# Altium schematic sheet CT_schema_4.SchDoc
size 578 x 363 mm
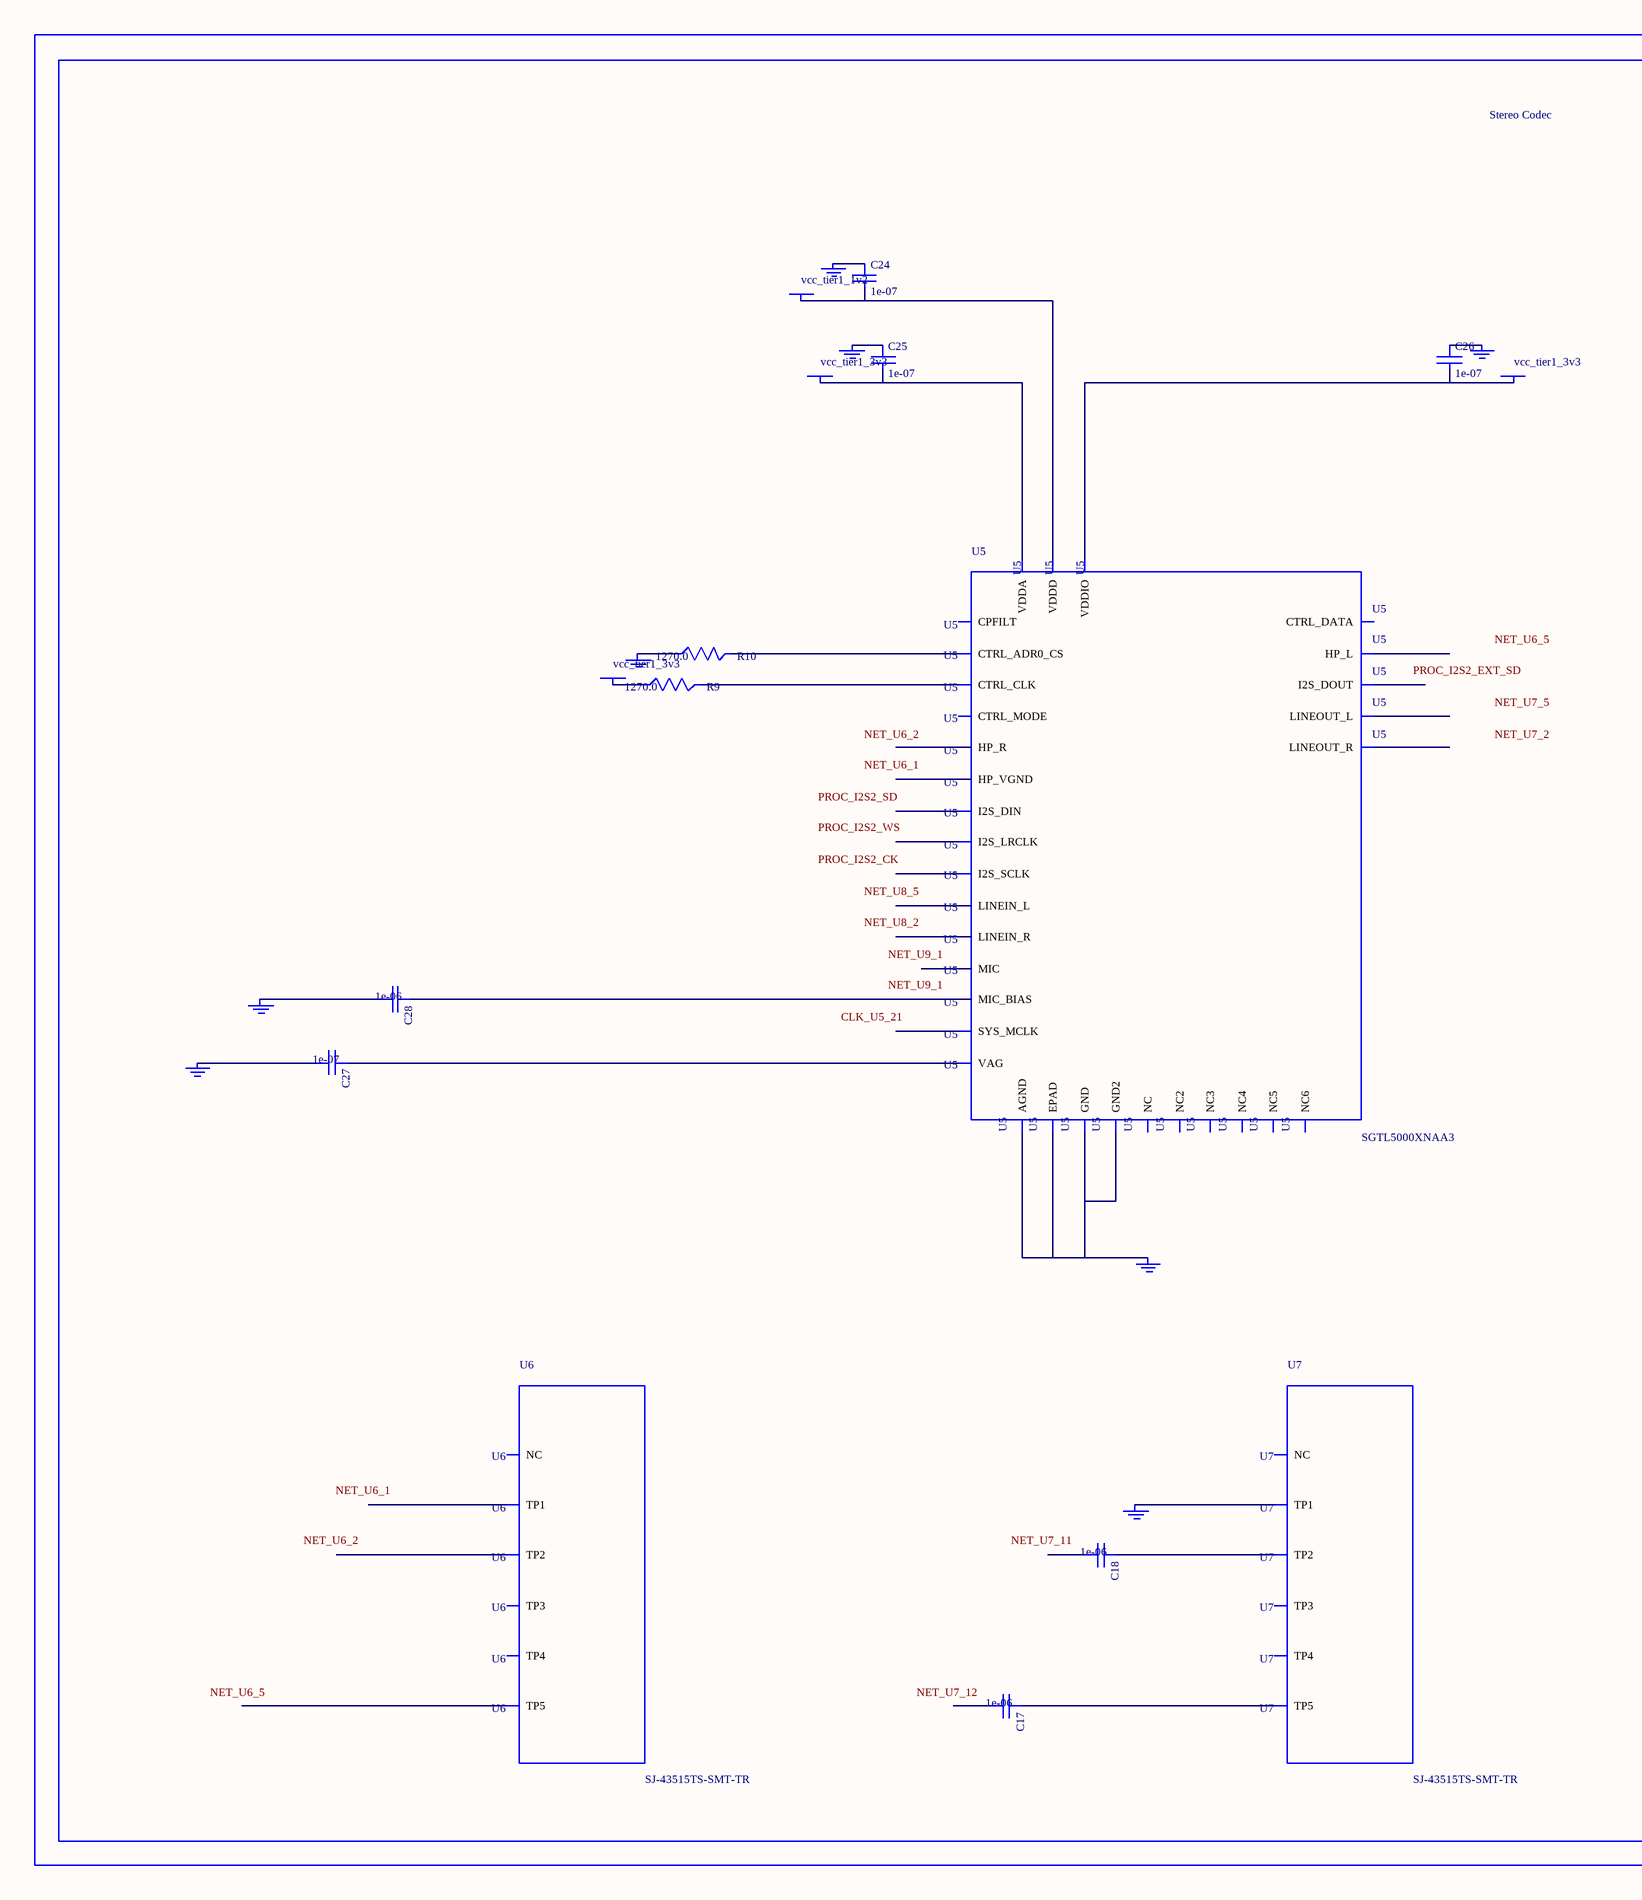
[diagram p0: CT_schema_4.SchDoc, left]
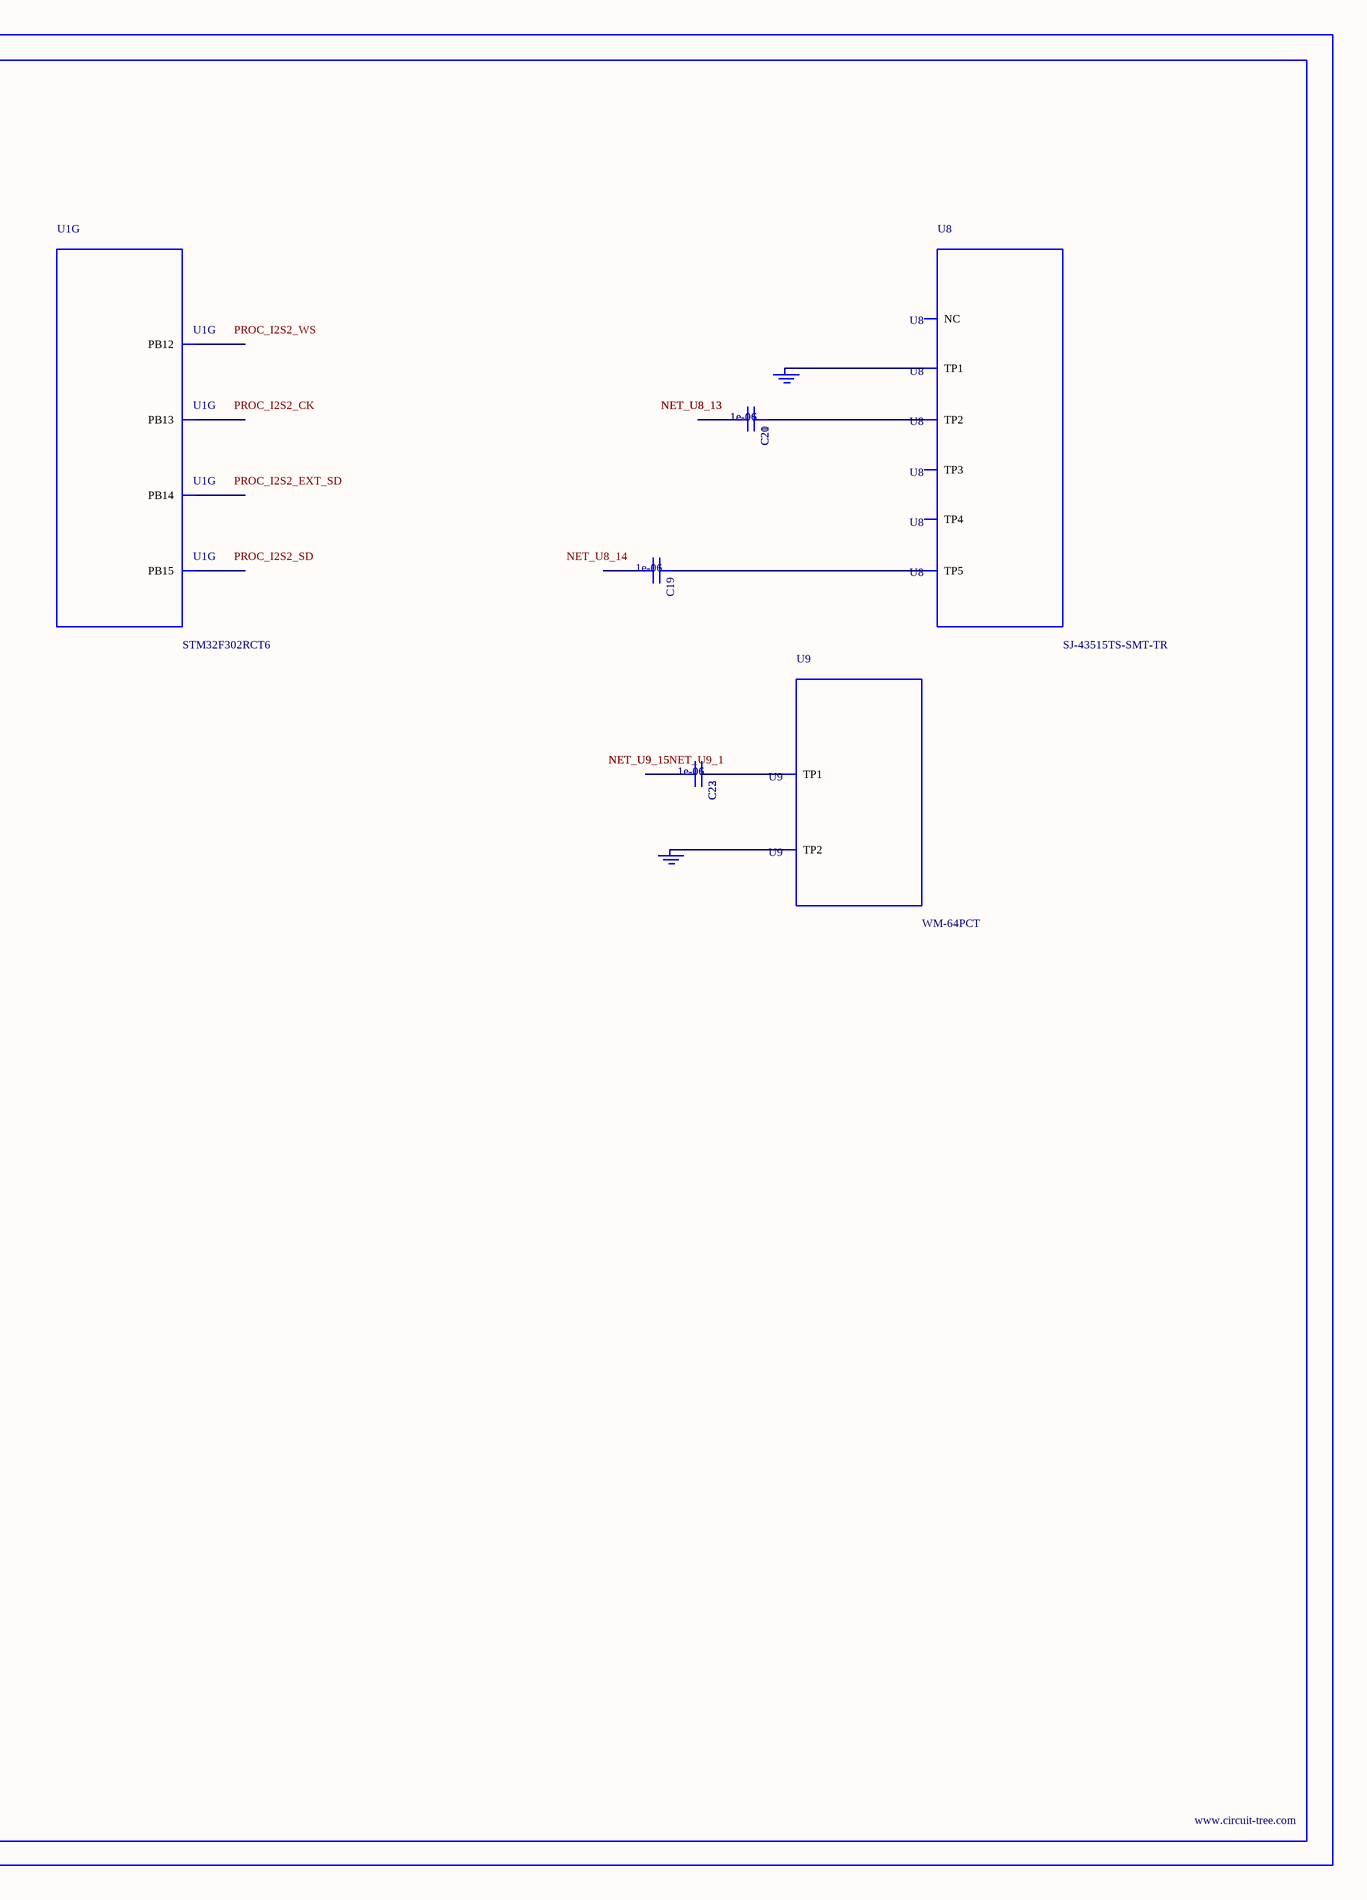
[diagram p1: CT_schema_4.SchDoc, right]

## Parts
BORDER3  (no value)
C17  1e-06  [C0603]
C18  1e-06  [C0603]
C19  1e-06  [C0603]
C20  1e-06  [C0603]
C21  1e-06  [C0603]
C22  1e-06  [C0603]
C23  1e-06  [C0603]
C24  1e-07  [C0402]
C25  1e-07  [C0402]
C26  1e-07  [C0402]
C27  1e-07  [C0402]
C28  1e-06  [C0603]
GND_INSTANCE_3_0  (no value)
GND_INSTANCE_3_1  (no value)
GND_INSTANCE_3_2  (no value)
GND_INSTANCE_3_3  (no value)
GND_INSTANCE_3_4  (no value)
GND_INSTANCE_3_5  (no value)
GND_INSTANCE_3_6  (no value)
GND_INSTANCE_3_7  (no value)
GND_INSTANCE_3_8  (no value)
GND_INSTANCE_3_9  (no value)
GND_INSTANCE_3_10  (no value)
POWER_INSTANCE_3_0  vcc_tier1_3v3
POWER_INSTANCE_3_1  vcc_tier1_3v3
POWER_INSTANCE_3_2  vcc_tier1_3v3
POWER_INSTANCE_3_3  vcc_tier1_1v2
R9  1270.0  [R0603]
R10  1270.0  [R0603]
U1  STM32F302RCT6  [LQFP64]  (part G of 8)
U5  SGTL5000XNAA3  [QFN-32]
U6  SJ-43515TS-SMT-TR  [SJ-43515TS-SMT-TR]
U7  SJ-43515TS-SMT-TR  [SJ-43515TS-SMT-TR]
U8  SJ-43515TS-SMT-TR  [SJ-43515TS-SMT-TR]
U9  WM-64PCT  [WM-64PC]

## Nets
NetC17_1: C17.1 U7.5(TP5)
NetC18_1: C18.1 U7.2(TP2)
NetC19_1: C19.1 U8.5(TP5)
NetC20_1: C20.1 C21.1 U8.2(TP2)
NetC20_2: C20.2 C21.2
NetC22_1: C22.1 C23.1 U9.1(TP1)
NetC22_2: C22.2 C23.2
NetC24_1: C24.1 GND_INSTANCE_3_5.0(GND)
NetC24_2: C24.2 POWER_INSTANCE_3_3.0(PWR) U5.30(VDDD)
NetC25_1: C25.1 GND_INSTANCE_3_1.0(GND)
NetC25_2: C25.2 POWER_INSTANCE_3_0.0(PWR) U5.5(VDDA)
NetC26_1: C26.1 GND_INSTANCE_3_4.0(GND)
NetC26_2: C26.2 POWER_INSTANCE_3_1.0(PWR) U5.20(VDDIO)
NetC27_1: C27.1 U5.10(VAG)
NetC27_2: C27.2 GND_INSTANCE_3_2.0(GND)
NetC28_1: C28.1 U5.16(MIC_BIAS)
NetC28_2: C28.2 GND_INSTANCE_3_3.0(GND)
NetGND_INSTANCE_3_0_0: GND_INSTANCE_3_0.0(GND) U5.1(GND) U5.3(GND2) U5.7(AGND) U5.EXP(EPAD)
NetGND_INSTANCE_3_6_0: GND_INSTANCE_3_6.0(GND) R10.1
NetGND_INSTANCE_3_7_0: GND_INSTANCE_3_7.0(GND) U7.1(TP1)
NetGND_INSTANCE_3_8_0: GND_INSTANCE_3_8.0(GND) GND_INSTANCE_3_9.0(GND) U8.1(TP1)
NetGND_INSTANCE_3_10_0: GND_INSTANCE_3_10.0(GND) U9.2(TP2)
NetPOWER_INSTANCE_3_2_0: POWER_INSTANCE_3_2.0(PWR) R9.1
NetR9_2: R9.2 U5.29(CTRL_CLK)
NetR10_2: R10.2 U5.31(CTRL_ADR0_CS)

Not connected (* = marked no-connect by the designer): C17 2; C18 2; C19 2; U1 33(PB12) 34(PB13) 35(PB14) 36(PB15); U5 2(HP_R) 4(HP_VGND) 6(HP_L) 8(NC) 9(NC2) 11(LINEOUT_R) 12(LINEOUT_L) 13(LINEIN_R) 14(LINEIN_L) 15(MIC) 17(NC3) 18(CPFILT) 19(NC4) 21(SYS_MCLK) 22(NC5) 23(I2S_LRCLK) 24(I2S_SCLK) 25(I2S_DOUT) 26(I2S_DIN) 27(CTRL_DATA) 28(NC6) 32(CTRL_MODE); U6 1(TP1) 2(TP2) 3(TP3) 4(TP4) 5(TP5) 6(NC); U7 3(TP3) 4(TP4) 6(NC); U8 3(TP3) 4(TP4) 6(NC)

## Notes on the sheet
- Labels drawn without touching a wire or pin: CLK_U5_21, NET_U6_1, NET_U6_2, NET_U6_5, NET_U7_2, NET_U7_5, NET_U7_11, NET_U7_12, NET_U8_2, NET_U8_5, NET_U8_14, NET_U9_1, PROC_I2S2_CK, PROC_I2S2_EXT_SD, PROC_I2S2_SD, PROC_I2S2_WS

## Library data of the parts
BORDER3 = BORDER_PAGE3
C17-C23 C28 = C0603C105K3RACTU
C24-C27 = C0402C104K3RACTU
GND_INSTANCE_3_0-GND_INSTANCE_3_10 = GND
POWER_INSTANCE_3_0-POWER_INSTANCE_3_3 = PWR
R9 R10 = RC0603FR-071K27L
